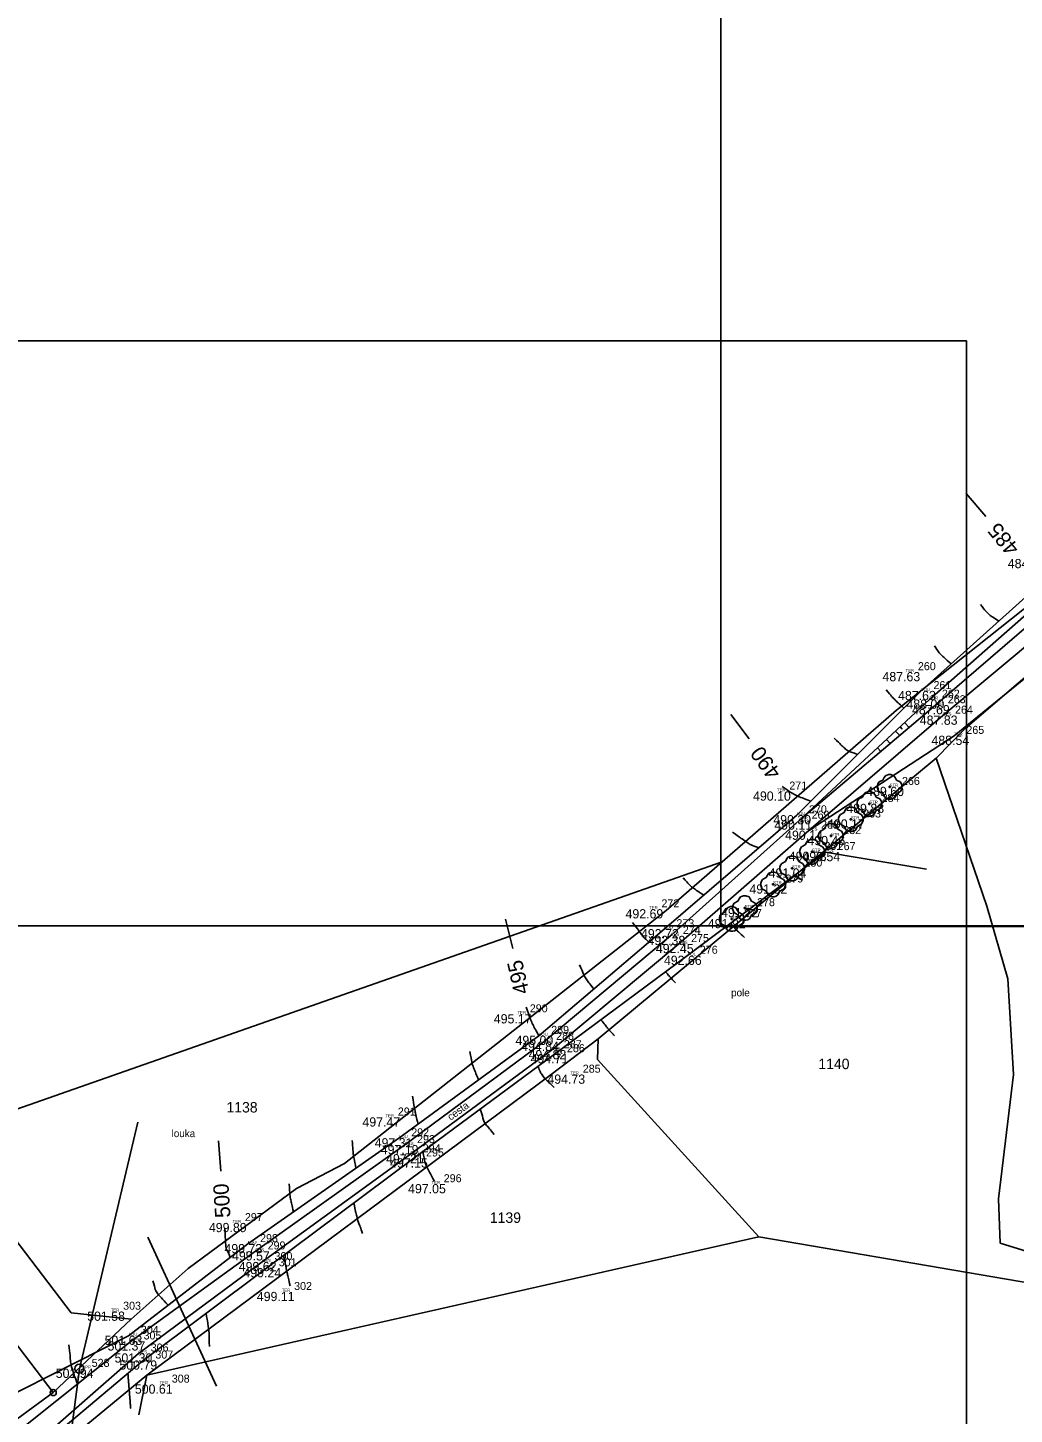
# Model space of a CAD drawing. Extents: x -604848 to -603227, y -1111879 to -1109838.
# Drawn here: x -603934 to -603773.6, y -1110757.2 to -1110531.9 of the extents above; entities that cross this region are included whole.
import ezdxf

# ---------------------------------------------------------------- set-up
doc = ezdxf.new("R2010")
doc.units = 0
for name, color, linetype in [('1', 7, 'Continuous'), ('10', 7, 'Continuous'), ('14', 7, 'Continuous'), ('18', 7, 'Continuous'), ('19', 7, 'Continuous'), ('20', 7, 'Continuous'), ('28', 7, 'Continuous'), ('3', 7, 'Continuous'), ('4', 7, 'Continuous'), ('5', 7, 'Continuous'), ('50', 7, 'Continuous'), ('7', 7, 'Continuous'), ('8', 7, 'Continuous'), ('9', 7, 'Continuous'), ('Default', 7, 'Continuous')]:
    doc.layers.add(name, color=color, linetype=linetype)

# ---------------------------------------------------------------- blocks, each defined once
blk = doc.blocks.new('Z101')
at = {"layer": '28'}
for radius in [0.75, 0.01]:
    blk.add_circle((0, 0), radius, dxfattribs=at)
blk = doc.blocks.new('Z105')
at = {"layer": '28'}
for radius in [0.5, 0.01]:
    blk.add_circle((0, 0), radius, dxfattribs=at)
blk = doc.blocks.new('POINT_DISPLAY')
at = {"layer": 'Default'}
blk.add_line((0, 0), (0, 0), dxfattribs=at)
blk = doc.blocks.new('Z313')
at = {"layer": '3'}
for p, q in [((-2, 0.2), (-1.9, 0.5)), ((-2, -0.2), (-2, 0.2)), ((-1.9, 0.5), (-1.7, 0.8)), ((-1.7, 0.8), (-1.1, 1.1)), ((-1.1, 1.1), (-0.9, 1.5)), ((-0.9, 1.5), (-0.7, 1.8)), ((-0.7, 1.8), (-0.2, 2)), ((-0.2, 2), (0.2, 2)), ((-0.1, -0.1), (-0.1, 0.1)), ((-0.1, 0.1), (0.1, 0.1)), ((0.1, 0.1), (0.1, -0.1)), ((0.2, 2), (0.7, 1.8)), ((0.7, 1.8), (0.9, 1.5)), ((0.9, 1.5), (1.1, 1.1)), ((1.1, 1.1), (1.7, 0.8)), ((1.7, 0.8), (1.9, 0.5)), ((1.9, 0.5), (2, 0.2)), ((2, 0.2), (2, -0.2)), ((-1.8, -0.7), (-2, -0.2)), ((-1.5, -0.9), (-1.8, -0.7)), ((-1.1, -1.1), (-1.5, -0.9)), ((-0.8, -1.7), (-1.1, -1.1)), ((-0.5, -1.9), (-0.8, -1.7)), ((-0.2, -2), (-0.5, -1.9)), ((0.2, -2), (-0.2, -2)), ((0.1, -0.1), (-0.1, -0.1)), ((0.5, -1.9), (0.2, -2)), ((0.8, -1.7), (0.5, -1.9)), ((1.1, -1.1), (0.8, -1.7)), ((1.5, -0.9), (1.1, -1.1)), ((1.8, -0.7), (1.5, -0.9)), ((2, -0.2), (1.8, -0.7))]:
    blk.add_line(p, q, dxfattribs=at)

msp = doc.modelspace()

# ---------------------------------------------------------------- linework, layer by layer
at = {"layer": '1'}
for p, q in [((-603792.75, -1110642.77), (-603746.35, -1110605.91)), ((-603781.58, -1110645.78), (-603768.87, -1110634.85)), ((-603821.12, -1110667.42), (-603792.75, -1110642.77)), ((-603786.31, -1110650.58), (-603781.58, -1110645.78)), ((-603841.27, -1110696.15), (-603786.31, -1110650.58)), ((-603778.07, -1110674.62), (-603786.31, -1110650.58)), ((-603948.31, -1110711.99), (-603821.12, -1110667.42)), ((-603821.12, -1110667.42), (-603830.23, -1110675.33)), ((-603830.23, -1110675.33), (-603882.48, -1110716.44)), ((-603774.65, -1110686.45), (-603778.07, -1110674.62)), ((-603773.75, -1110701.99), (-603774.65, -1110686.45)), ((-603848.87, -1110701.97), (-603841.27, -1110696.15)), ((-603841.36, -1110699.55), (-603841.27, -1110696.15)), ((-603815.14, -1110728.36), (-603841.36, -1110699.55)), ((-603914.6, -1110750.81), (-603848.87, -1110701.97)), ((-603776.2, -1110722.15), (-603773.75, -1110701.99)), ((-603926.93, -1110740.69), (-603945.51, -1110716.34)), ((-603882.48, -1110716.44), (-603890.29, -1110720.5)), ((-603890.29, -1110720.5), (-603907.88, -1110733.51)), ((-603775.93, -1110729.36), (-603776.2, -1110722.15)), ((-603815.14, -1110728.36), (-603914.6, -1110750.81)), ((-603914.43, -1110728.42), (-603903.27, -1110752.6)), ((-603767.78, -1110736.44), (-603815.14, -1110728.36)), ((-603767.78, -1110731.89), (-603775.93, -1110729.36)), ((-603944.79, -1110734.04), (-603929.83, -1110753.64)), ((-603907.88, -1110733.51), (-603917.14, -1110741.73)), ((-603917.14, -1110741.73), (-603926.93, -1110740.69)), ((-603929.83, -1110753.64), (-603917.14, -1110741.73)), ((-603927.94, -1110761.8), (-603914.6, -1110750.81)), ((-603915.91, -1110757.23), (-603914.6, -1110750.81)), ((-603929.83, -1110753.64), (-604011.5, -1110813.05))]:
    msp.add_line(p, q, dxfattribs=at)
for points in [[(-603752.05, -1110677.81), (-603752.05, -1109837.81), (-604346.05, -1109837.81), (-604346.05, -1110677.81), (-603752.05, -1110677.81)], [(-603227.31, -1110677.93), (-603227.31, -1109837.93), (-603821.31, -1109837.93), (-603821.31, -1110677.93), (-603227.31, -1110677.93)], [(-603781.41, -1111422.77), (-603781.41, -1110582.77), (-604375.41, -1110582.77), (-604375.41, -1111422.77), (-603781.41, -1111422.77)]]:
    msp.add_lwpolyline(points, dxfattribs=at)
at = {"layer": '10'}
for p, q in [((-603788.75, -1110639.65), (-603768.59, -1110621.54)), ((-603808.99, -1110659.83), (-603788.75, -1110639.65)), ((-603830.54, -1110678.34), (-603808.99, -1110659.83)), ((-603804.33, -1110665.82), (-603826.73, -1110682.66)), ((-603804.33, -1110665.82), (-603787.89, -1110668.6)), ((-603850.89, -1110695.67), (-603830.54, -1110678.34)), ((-603826.73, -1110682.66), (-603848.33, -1110698.64)), ((-603873.64, -1110712.31), (-603850.89, -1110695.67)), ((-603848.33, -1110698.64), (-603871.23, -1110715.58)), ((-603898.21, -1110729.5), (-603873.64, -1110712.31)), ((-603871.23, -1110715.58), (-603895.18, -1110733.42)), ((-603917.59, -1110744.4), (-603898.21, -1110729.5)), ((-603895.18, -1110733.42), (-603915.23, -1110748.42)), ((-603939.62, -1110755.58), (-603917.59, -1110744.4)), ((-603932.66, -1110763.08), (-603915.23, -1110748.42))]:
    msp.add_line(p, q, dxfattribs=at)
at = {"layer": '4'}
for p, q in [((-603786.43, -1110641.95), (-603766.46, -1110624.76)), ((-603764.85, -1110626.62), (-603785.26, -1110643.65)), ((-603808.57, -1110660.7), (-603786.43, -1110641.95)), ((-603785.26, -1110643.65), (-603807.04, -1110662.34)), ((-603829.49, -1110679.44), (-603808.57, -1110660.7)), ((-603807.04, -1110662.34), (-603828.15, -1110680.75)), ((-603850.09, -1110696.64), (-603829.49, -1110679.44)), ((-603828.15, -1110680.75), (-603848.84, -1110697.99)), ((-603872.69, -1110713.41), (-603850.09, -1110696.64)), ((-603848.84, -1110697.99), (-603871.78, -1110714.91)), ((-603896.98, -1110730.68), (-603872.69, -1110713.41)), ((-603871.78, -1110714.91), (-603895.86, -1110732.42)), ((-603917.15, -1110745.31), (-603896.98, -1110730.68)), ((-603895.86, -1110732.42), (-603915.99, -1110747.27)), ((-603917.15, -1110745.31), (-603935.4, -1110759.85)), ((-603915.99, -1110747.27), (-603933.26, -1110762.43))]:
    msp.add_line(p, q, dxfattribs=at)
at = {"layer": '5'}
for q in [(-603916.1, -1110709.73), (-603930.49, -1110788.14)]:
    msp.add_line((-603925.58, -1110749.76), q, dxfattribs=at)
at = {"layer": '7'}
for p, q in [((-603778.26, -1110611.31), (-603781.47, -1110607.57)), ((-603787.39, -1110641.05), (-603767.35, -1110623.39)), ((-603783.41, -1110646.93), (-603761.85, -1110629.41)), ((-603808.57, -1110660.7), (-603787.39, -1110641.05)), ((-603816.74, -1110647.41), (-603819.71, -1110643.47)), ((-603783.41, -1110646.93), (-603807.04, -1110662.34)), ((-603855.15, -1110681.51), (-603856.31, -1110676.72)), ((-603902.57, -1110717.67), (-603902.97, -1110712.75))]:
    msp.add_line(p, q, dxfattribs=at)
for points, degree in [([(-603776.14, -1110628.31), (-603776.68, -1110627.93), (-603777.28, -1110627.6), (-603777.77, -1110627.16), (-603778.28, -1110626.7), (-603778.68, -1110626.13), (-603779.14, -1110625.62)], 3), ([(-603783.87, -1110635.26), (-603784.42, -1110634.77), (-603784.97, -1110634.28), (-603785.52, -1110633.79), (-603785.97, -1110633.39), (-603786.24, -1110632.83), (-603786.6, -1110632.35)], 3), ([(-603791.55, -1110642.44), (-603792.04, -1110641.99), (-603792.57, -1110641.57), (-603793.03, -1110641.09), (-603793.53, -1110640.59), (-603793.96, -1110640.03), (-603794.43, -1110639.49)], 3), ([(-603799.12, -1110649.99), (-603799.81, -1110649.65), (-603800.64, -1110649.51), (-603801.19, -1110648.98), (-603801.75, -1110648.43), (-603802.31, -1110647.89), (-603802.88, -1110647.34)], 3), ([(-603806.69, -1110657.54), (-603807.55, -1110657.21), (-603808.42, -1110656.94), (-603809.25, -1110656.53), (-603810, -1110656.17), (-603810.64, -1110655.63), (-603811.33, -1110655.18)], 3), ([(-603815.17, -1110665.14), (-603815.78, -1110664.87), (-603816.46, -1110664.7), (-603817, -1110664.31), (-603817.8, -1110663.75), (-603818.6, -1110663.19), (-603819.4, -1110662.62)], 3), ([(-603824.11, -1110672.82), (-603824.71, -1110672.41), (-603825.34, -1110672.03), (-603825.92, -1110671.58), (-603826.5, -1110671.14), (-603826.93, -1110670.54), (-603827.43, -1110670.02)], 3), ([(-603808.04, -1110670.46), (-603808.33, -1110670.24), (-603808.63, -1110670.05), (-603808.92, -1110669.82), (-603809.03, -1110669.72), (-603809.12, -1110669.6), (-603809.22, -1110669.49)], 3), ([(-603833.03, -1110680.46), (-603833.42, -1110680.06), (-603833.86, -1110679.71), (-603834.19, -1110679.26), (-603834.68, -1110678.59), (-603835.17, -1110677.92), (-603835.66, -1110677.25)], 3), ([(-603817.46, -1110679.72), (-603817.91, -1110679.3), (-603818.38, -1110678.89), (-603818.81, -1110678.45), (-603819.13, -1110678.11), (-603819.43, -1110677.75), (-603819.75, -1110677.4)], 3), ([(-603841.97, -1110688.08), (-603842.38, -1110687.54), (-603842.83, -1110687.03), (-603843.18, -1110686.46), (-603843.63, -1110685.72), (-603843.93, -1110684.91), (-603844.3, -1110684.14)], 3), ([(-603828.7, -1110687.08), (-603829.08, -1110686.66), (-603829.48, -1110686.25), (-603829.85, -1110685.82), (-603830, -1110685.64), (-603830.15, -1110685.47), (-603830.29, -1110685.29)], 3), ([(-603850.89, -1110695.67), (-603851.24, -1110695.01), (-603851.63, -1110694.37), (-603851.95, -1110693.69), (-603852.35, -1110692.83), (-603852.61, -1110691.92), (-603852.95, -1110691.03)], 3), ([(-603838.59, -1110695.71), (-603838.75, -1110695.53), (-603838.91, -1110695.35), (-603839.07, -1110695.18), (-603839.69, -1110694.51), (-603840.23, -1110693.77), (-603840.8, -1110693.07)], 3), ([(-603860.72, -1110702.86), (-603860.98, -1110702.19), (-603861.24, -1110701.53), (-603861.51, -1110700.86), (-603861.83, -1110700.02), (-603861.93, -1110699.11), (-603862.14, -1110698.24)], 3), ([(-603848.43, -1110704.07), (-603849.1, -1110703.36), (-603849.89, -1110702.74), (-603850.43, -1110701.95), (-603850.7, -1110701.56), (-603850.84, -1110701.08), (-603851.05, -1110700.65)], 3), ([(-603870.52, -1110710.02), (-603870.67, -1110709.39), (-603870.86, -1110708.76), (-603870.98, -1110708.12), (-603871.14, -1110707.25), (-603871.28, -1110706.38), (-603871.43, -1110705.5)], 3), ([(-603858.14, -1110711.72), (-603858.55, -1110711.24), (-603858.95, -1110710.75), (-603859.36, -1110710.27), (-603859.98, -1110709.54), (-603860.07, -1110708.49), (-603860.43, -1110707.59)], 3), ([(-603880.63, -1110717.2), (-603880.77, -1110716.41), (-603880.95, -1110715.62), (-603881.06, -1110714.82), (-603881.15, -1110714.11), (-603881.18, -1110713.39), (-603881.24, -1110712.67)], 3), ([(-603867.85, -1110719.37), (-603868.27, -1110718.58), (-603868.68, -1110717.79), (-603869.09, -1110716.99), (-603869.49, -1110716.23), (-603869.53, -1110715.32), (-603869.76, -1110714.49)], 3), ([(-603890.77, -1110724.3), (-603890.92, -1110723.66), (-603891.07, -1110723.03), (-603891.21, -1110722.39), (-603891.41, -1110721.52), (-603891.41, -1110720.63), (-603891.5, -1110719.75)], 3), ([(-603879.54, -1110727.82), (-603879.86, -1110726.87), (-603880.27, -1110725.94), (-603880.51, -1110724.96), (-603880.69, -1110724.26), (-603880.82, -1110723.55), (-603880.98, -1110722.84)], 3), ([(-603901.05, -1110731.69), (-603901.29, -1110731), (-603901.75, -1110730.35), (-603901.79, -1110729.62), (-603901.85, -1110728.74), (-603901.88, -1110727.86), (-603901.92, -1110726.98)], 3), ([(-603891.33, -1110736.31), (-603891.56, -1110735.28), (-603891.79, -1110734.25), (-603892.01, -1110733.22), (-603892.14, -1110732.6), (-603892.27, -1110731.97), (-603892.41, -1110731.35)], 3), ([(-603911.15, -1110739.45), (-603911.71, -1110738.82), (-603912.3, -1110738.22), (-603912.84, -1110737.57), (-603913.32, -1110737), (-603913.37, -1110736.19), (-603913.63, -1110735.5)], 3), ([(-603904.43, -1110746.17), (-603904.49, -1110745.17), (-603904.46, -1110744.16), (-603904.6, -1110743.17), (-603904.71, -1110742.36), (-603904.85, -1110741.55), (-603904.98, -1110740.75)], 3), ([(-603925.9, -1110752.29), (-603926.14, -1110751.59), (-603926.38, -1110750.89), (-603926.62, -1110750.19), (-603927.09, -1110748.81), (-603927.07, -1110747.31), (-603927.3, -1110745.86)], 3), ([(-603917.7, -1110750.49), (-603917.54, -1110752.42), (-603917.39, -1110754.33), (-603917.24, -1110756.25)], 2)]:
    msp.add_open_spline(points, degree=degree, dxfattribs=at)
at = {"layer": '8'}
for p, q in [((-603792.91, -1110646.17), (-603792.25, -1110646.88)), ((-603792.17, -1110645.49), (-603791.83, -1110645.86)), ((-603791.44, -1110644.81), (-603790.72, -1110645.59)), ((-603795.84, -1110648.89), (-603795.31, -1110649.47)), ((-603794.37, -1110647.53), (-603793.78, -1110648.18))]:
    msp.add_line(p, q, dxfattribs=at)

# ---------------------------------------------------------------- block references
at = {"layer": '18'}
for p in [(-603791.29, -1110636.58), (-603788.75, -1110639.65), (-603787.39, -1110641.05), (-603786.43, -1110641.95), (-603785.26, -1110643.65), (-603783.41, -1110646.93), (-603793.88, -1110655.23), (-603812.19, -1110655.98), (-603808.99, -1110659.83), (-603797.18, -1110657.99), (-603808.57, -1110660.7), (-603807.04, -1110662.34), (-603800.19, -1110660.51), (-603803.42, -1110663.21), (-603806.49, -1110665.77), (-603804.33, -1110665.82), (-603809.73, -1110668.48), (-603812.83, -1110671.08), (-603832.97, -1110675.11), (-603817.43, -1110674.92), (-603819.56, -1110676.7), (-603830.54, -1110678.34), (-603829.49, -1110679.44), (-603828.15, -1110680.75), (-603826.73, -1110682.66), (-603854.37, -1110692.17), (-603850.89, -1110695.67), (-603850.09, -1110696.64), (-603848.84, -1110697.99), (-603848.33, -1110698.64), (-603845.76, -1110701.97), (-603875.82, -1110708.93), (-603873.64, -1110712.31), (-603872.69, -1110713.41), (-603871.78, -1110714.91), (-603871.23, -1110715.58), (-603868.36, -1110719.77), (-603900.68, -1110726.08), (-603898.21, -1110729.5), (-603896.98, -1110730.68), (-603895.86, -1110732.42), (-603895.18, -1110733.42), (-603892.68, -1110737.28), (-603920.47, -1110740.48), (-603917.59, -1110744.4), (-603917.15, -1110745.31), (-603915.99, -1110747.27), (-603925.58, -1110749.76), (-603915.23, -1110748.42), (-603912.56, -1110752.32)]:
    msp.add_blockref('POINT_DISPLAY', p, dxfattribs=at)
at = {"layer": '28'}
for name, p in [('Z101', (-603925.58, -1110749.76)), ('Z105', (-603929.83, -1110753.64))]:
    msp.add_blockref(name, p, dxfattribs=at)
at = {"layer": '3'}
for p in [(-603793.88, -1110655.23), (-603797.18, -1110657.99), (-603800.19, -1110660.51), (-603803.42, -1110663.21), (-603806.49, -1110665.77), (-603809.73, -1110668.48), (-603812.83, -1110671.08), (-603817.43, -1110674.92), (-603819.56, -1110676.7)]:
    msp.add_blockref('Z313', p, dxfattribs=at)
at = {"layer": '50'}
msp.add_blockref('POINT_DISPLAY', (-603925.82, -1110752.22), dxfattribs=at)

# ---------------------------------------------------------------- texts
at = {"layer": '14'}
for s, p in [('1140', (-603805.47, -1110701.1)), ('1138', (-603901.67, -1110708.14)), ('1139', (-603858.86, -1110726.07))]:
    msp.add_text(s, height=1.7, dxfattribs=at).set_placement(p)
at = {"layer": '18'}
for s, p in [('TER', (-603791.29, -1110636.58)), ('LOU', (-603788.75, -1110639.65)), ('TER', (-603787.39, -1110641.05)), ('CES', (-603786.43, -1110641.95)), ('CES', (-603785.26, -1110643.65)), ('TER', (-603783.41, -1110646.93)), ('TER', (-603812.19, -1110655.98)), ('STR', (-603793.88, -1110655.23)), ('STR', (-603797.18, -1110657.99)), ('LOU', (-603808.99, -1110659.83)), ('STR', (-603800.19, -1110660.51)), ('CES', (-603808.57, -1110660.7)), ('CES', (-603807.04, -1110662.34)), ('STR', (-603803.42, -1110663.21)), ('STR', (-603806.49, -1110665.77)), ('POL', (-603804.33, -1110665.82)), ('STR', (-603809.73, -1110668.48)), ('STR', (-603812.83, -1110671.08)), ('TER', (-603832.97, -1110675.11)), ('STR', (-603817.43, -1110674.92)), ('LOU', (-603830.54, -1110678.34)), ('STR', (-603819.56, -1110676.7)), ('CES', (-603829.49, -1110679.44)), ('CES', (-603828.15, -1110680.75)), ('POL', (-603826.73, -1110682.66)), ('TER', (-603854.37, -1110692.17)), ('LOU', (-603850.89, -1110695.67)), ('CES', (-603850.09, -1110696.64)), ('CES', (-603848.84, -1110697.99)), ('POL', (-603848.33, -1110698.64)), ('TER', (-603845.76, -1110701.97)), ('TER', (-603875.82, -1110708.93)), ('LOU', (-603873.64, -1110712.31)), ('CES', (-603872.69, -1110713.41)), ('CES', (-603871.78, -1110714.91)), ('POL', (-603871.23, -1110715.58)), ('TER', (-603868.36, -1110719.77)), ('TER', (-603900.68, -1110726.08)), ('LOU', (-603898.21, -1110729.5)), ('CES', (-603896.98, -1110730.68)), ('CES', (-603895.86, -1110732.42)), ('POL', (-603895.18, -1110733.42)), ('TER', (-603892.68, -1110737.28)), ('TER', (-603920.47, -1110740.48)), ('LOU', (-603917.59, -1110744.4)), ('CES', (-603917.15, -1110745.31)), ('CES', (-603915.99, -1110747.27)), ('POL', (-603915.23, -1110748.42)), ('PBPP', (-603925.58, -1110749.76)), ('TER', (-603912.56, -1110752.32))]:
    msp.add_text(s, height=0.5, dxfattribs=at).set_placement(p)
at = {"layer": '19'}
for s, p in [('260', (-603789.29, -1110636.28)), ('261', (-603786.75, -1110639.35)), ('262', (-603785.39, -1110640.75)), ('263', (-603784.43, -1110641.65)), ('264', (-603783.26, -1110643.35)), ('265', (-603781.41, -1110646.63)), ('271', (-603810.19, -1110655.68)), ('266', (-603791.88, -1110654.93)), ('284', (-603795.18, -1110657.69)), ('270', (-603806.99, -1110659.53)), ('269', (-603806.57, -1110660.41)), ('283', (-603798.19, -1110660.21)), ('268', (-603805.04, -1110662.04)), ('282', (-603801.42, -1110662.91)), ('281', (-603804.49, -1110665.47)), ('267', (-603802.33, -1110665.52)), ('280', (-603807.73, -1110668.19)), ('279', (-603810.83, -1110670.78)), ('272', (-603830.97, -1110674.81)), ('278', (-603815.43, -1110674.62)), ('277', (-603817.56, -1110676.4)), ('273', (-603828.54, -1110678.04)), ('274', (-603827.49, -1110679.14)), ('275', (-603826.15, -1110680.45)), ('276', (-603824.73, -1110682.35)), ('290', (-603852.37, -1110691.87)), ('289', (-603848.89, -1110695.37)), ('288', (-603848.09, -1110696.34)), ('287', (-603846.84, -1110697.69)), ('286', (-603846.33, -1110698.34)), ('285', (-603843.76, -1110701.67)), ('291', (-603873.82, -1110708.63)), ('292', (-603871.64, -1110712.01)), ('293', (-603870.69, -1110713.11)), ('294', (-603869.78, -1110714.61)), ('295', (-603869.23, -1110715.28)), ('296', (-603866.36, -1110719.47)), ('297', (-603898.68, -1110725.78)), ('298', (-603896.21, -1110729.2)), ('299', (-603894.98, -1110730.38)), ('300', (-603893.86, -1110732.12)), ('301', (-603893.18, -1110733.12)), ('302', (-603890.68, -1110736.98)), ('303', (-603918.47, -1110740.18)), ('304', (-603915.59, -1110744.1)), ('305', (-603915.15, -1110745.01)), ('306', (-603913.99, -1110746.97)), ('307', (-603913.23, -1110748.12)), ('528', (-603923.58, -1110749.46)), ('308', (-603910.56, -1110752.02))]:
    msp.add_text(s, height=1.3, dxfattribs=at).set_placement(p)
at = {"layer": '20'}
for s, p in [('484.90 ', (-603774.68, -1110619.71)), ('487.63 ', (-603795.05, -1110638.08)), ('487.63 ', (-603792.51, -1110641.15)), ('488.00 ', (-603791.15, -1110642.55)), ('487.69 ', (-603790.25, -1110643.45)), ('487.83 ', (-603788.98, -1110645.15)), ('488.54 ', (-603787.08, -1110648.43)), ('489.60 ', (-603797.69, -1110656.73)), ('490.10 ', (-603816.08, -1110657.48)), ('490.30 ', (-603812.79, -1110661.33)), ('489.88 ', (-603800.92, -1110659.49)), ('490.11 ', (-603812.62, -1110662.2)), ('490.14 ', (-603810.87, -1110663.84)), ('490.17 ', (-603804.06, -1110662.01)), ('490.46 ', (-603807.24, -1110664.71)), ('490.73 ', (-603810.27, -1110667.27)), ('490.54 ', (-603808.06, -1110667.32)), ('491.04 ', (-603813.55, -1110669.98)), ('491.32 ', (-603816.67, -1110672.58)), ('492.69 ', (-603836.81, -1110676.61)), ('491.72 ', (-603821.28, -1110676.42)), ('491.92 ', (-603823.43, -1110678.2)), ('492.72 ', (-603834.3, -1110679.84)), ('492.38 ', (-603833.24, -1110680.94)), ('492.45 ', (-603831.88, -1110682.25)), ('492.66 ', (-603830.57, -1110684.16)), ('495.17 ', (-603858.22, -1110693.67)), ('495.00 ', (-603854.69, -1110697.17)), ('494.84 ', (-603853.78, -1110698.14)), ('494.82 ', (-603852.57, -1110699.49)), ('494.71 ', (-603852.25, -1110700.14)), ('494.73 ', (-603849.51, -1110703.47)), ('497.47 ', (-603879.57, -1110710.43)), ('497.31 ', (-603877.58, -1110713.81)), ('497.19 ', (-603876.6, -1110714.91)), ('497.21 ', (-603875.73, -1110716.41)), ('497.15 ', (-603875.08, -1110717.08)), ('497.05 ', (-603872.15, -1110721.27)), ('499.89 ', (-603904.53, -1110727.58)), ('499.73 ', (-603902, -1110731)), ('499.57 ', (-603900.77, -1110732.18)), ('499.62 ', (-603899.68, -1110733.92)), ('499.24 ', (-603898.92, -1110734.92)), ('499.11 ', (-603896.74, -1110738.78)), ('501.58 ', (-603924.31, -1110741.98)), ('501.63 ', (-603921.48, -1110745.9)), ('501.37 ', (-603921, -1110746.81)), ('501.30 ', (-603919.86, -1110748.77)), ('501.94 ', (-603929.42, -1110751.26)), ('500.79 ', (-603919.08, -1110749.92)), ('500.61 ', (-603916.56, -1110753.82))]:
    msp.add_text(s, height=1.5, dxfattribs=at).set_placement(p)
at = {"layer": '7'}
for s, rotation, p in [('485', 129.6, (-603772.65, -1110616.38)), ('490', 126, (-603811.4, -1110652.9)), ('495', 102.6, (-603852.44, -1110688.63)), ('500', 93.6, (-603901.01, -1110725.17))]:
    msp.add_text(s, height=2.5, rotation=rotation, dxfattribs=at).set_placement(p)
at = {"layer": '9'}
for s, p in [('pole', (-603819.65, -1110689.27)), ('louka', (-603910.59, -1110712.14))]:
    msp.add_text(s, height=1.2, dxfattribs=at).set_placement(p)
msp.add_text('cesta', height=1.2, rotation=36, dxfattribs=at).set_placement((-603865.23, -1110709.5))

doc.saveas('drawing.dxf')
